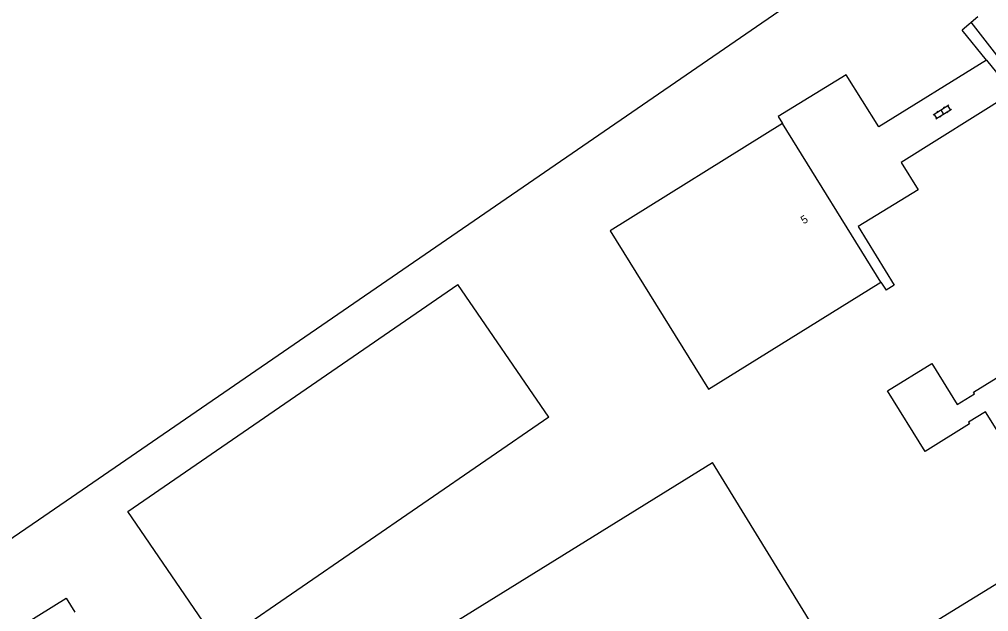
# Model space of a CAD drawing. Extents: x 136000 to 141000, y 400494 to 402006.
# Drawn here: x 136393.6 to 136514.7, y 401405.3 to 401479.3 of the extents above; entities that cross this region are included whole.
import ezdxf

# ---------------------------------------------------------------- set-up
doc = ezdxf.new("R2010")
doc.units = 0
for name, color, linetype in [('gg-afsc-hekwerk', 7, 'Continuous'), ('gg-anno-huisnummerreeks BGT', 7, 'Continuous'), ('gg-bbg-bijgebouw', 7, 'Continuous'), ('gg-bbg-gedigitaliseerde bebouwing', 7, 'Continuous'), ('gg-bbg-gedigitaliseerde bijgebouw', 7, 'Continuous'), ('gg-bbg-hoofdgebouw', 7, 'Continuous'), ('gg-knt-bronhoudergrens', 7, 'Continuous'), ('gg-knt-verharding', 7, 'Continuous'), ('gg-kwrk-duiker nz buis', 7, 'Continuous'), ('gt-grn-groengrens', 7, 'Continuous'), ('gt-grn-vlakafsluiter', 7, 'Continuous'), ('gt-symb-klinker verharding', 7, 'Continuous')]:
    doc.layers.add(name, color=color, linetype=linetype)

# ---------------------------------------------------------------- blocks, each defined once
blk = doc.blocks.new('gt0-KL1')
at = {"layer": 'gt-symb-klinker verharding'}
for p, q in [((-1.15, 0.3), (1.15, 0.3)), ((-1, -0.3), (-1, 0.3)), ((-0.5, 0.3), (-0.5, 0.45)), ((0, -0.3), (0, 0.3)), ((0.5, 0.3), (0.5, 0.45)), ((1, -0.3), (1, 0.3)), ((-1.15, -0.3), (1.15, -0.3)), ((-0.5, -0.45), (-0.5, -0.3)), ((0.5, -0.45), (0.5, -0.3))]:
    blk.add_line(p, q, dxfattribs=at)

msp = doc.modelspace()

# ---------------------------------------------------------------- linework, layer by layer
at = {"layer": 'gg-afsc-hekwerk'}
msp.add_line((136501.29, 401446.45), (136501.92, 401445.42), dxfattribs=at)
msp.add_line((136501.29, 401446.45), (136501.92, 401445.42), dxfattribs=at)
at = {"layer": 'gg-bbg-bijgebouw'}
msp.add_line((136459.79, 401429.58), (136448.42, 401446.13), dxfattribs=at)
at = {"layer": 'gg-bbg-gedigitaliseerde bebouwing'}
for p, q in [((136467.43, 401452.85), (136479.73, 401433.06)), ((136479.73, 401433.06), (136501.29, 401446.45))]:
    msp.add_line(p, q, dxfattribs=at)
at = {"layer": 'gg-bbg-gedigitaliseerde bijgebouw'}
for p, q in [((136407.15, 401417.78), (136448.42, 401446.13)), ((136459.79, 401429.58), (136418.51, 401401.23)), ((136418.51, 401401.23), (136407.15, 401417.78))]:
    msp.add_line(p, q, dxfattribs=at)
at = {"layer": 'gg-bbg-hoofdgebouw'}
for p, q in [((136488.98, 401466.24), (136467.43, 401452.85)), ((136501.29, 401446.45), (136488.98, 401466.24))]:
    msp.add_line(p, q, dxfattribs=at)
msp.add_lwpolyline([(136507.63, 401436.29), (136510.83, 401431.17), (136512.96, 401432.49), (136512.84, 401432.68), (136520.48, 401437.42), (136528.4, 401424.7), (136520.79, 401419.95), (136514.36, 401430.25), (136512.23, 401428.93), (136512.34, 401428.75), (136506.82, 401425.3), (136502.12, 401432.85), (136507.63, 401436.29)], dxfattribs=at)
at = {"layer": 'gg-knt-bronhoudergrens'}
msp.add_lwpolyline([(136287.96, 401342.74), (136288.4, 401343.21), (136395.98, 401416.73), (136502.78, 401490.13)], dxfattribs=at)
at = {"layer": 'gg-knt-verharding'}
for p, q in [((136513.4, 401479.59), (136511.42, 401477.9)), ((136514.46, 401474.15), (136511.42, 401477.9)), ((136514.46, 401474.15), (136517.73, 401470.12)), ((136517.73, 401470.12), (136503.81, 401461.37))]:
    msp.add_line(p, q, dxfattribs=at)
for points in [[(136514.46, 401474.15), (136501.02, 401465.84), (136496.93, 401472.33), (136488.42, 401467.11), (136488.98, 401466.24)], [(136503.81, 401461.37), (136505.93, 401457.97), (136498.45, 401453.38), (136502.95, 401446.05), (136501.92, 401445.42)], [(136276.93, 401349.16), (136287.03, 401339.55), (136288.47, 401340.88), (136288.71, 401340.62), (136289.84, 401341.11), (136298.15, 401346.24), (136299.14, 401344.62), (136399.47, 401406.95), (136400.55, 401405.21)]]:
    msp.add_lwpolyline(points, dxfattribs=at)
at = {"layer": 'gg-kwrk-duiker nz buis'}
msp.add_line((136519.67, 401469.72), (136512.55, 401478.93), dxfattribs=at)
at = {"layer": 'gt-grn-groengrens'}
msp.add_lwpolyline([(136562.37, 401402.8), (136545.7, 401427.16), (136496.72, 401397.05), (136480.22, 401423.9)], dxfattribs=at)
at = {"layer": 'gt-grn-vlakafsluiter'}
msp.add_lwpolyline([(136420.38, 401387.27), (136420.59, 401387), (136480.22, 401423.9)], dxfattribs=at)

# ---------------------------------------------------------------- block references
at = {"layer": 'gt-symb-klinker verharding', "rotation": 32.13289585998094}
msp.add_blockref('gt0-KL1', (136508.96, 401467.7), dxfattribs=at)

# ---------------------------------------------------------------- texts
at = {"layer": 'gg-anno-huisnummerreeks BGT'}
msp.add_text('5', height=1, rotation=31.9, dxfattribs=at).set_placement((136491.64, 401453.65))

doc.saveas('drawing.dxf')
